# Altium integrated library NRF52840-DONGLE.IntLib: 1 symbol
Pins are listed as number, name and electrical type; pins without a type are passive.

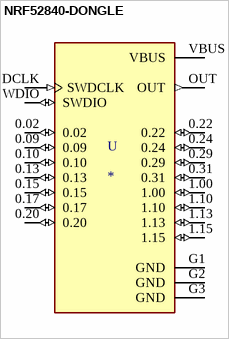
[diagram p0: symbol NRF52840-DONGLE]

## NRF52840-DONGLE
designator U
- Transceiver; BluetoothÂ® 5 For Use With nRF52840; MF: Nordic Semiconductor; MP: NRF52840-DONGLE
footprint MODULE_NRF52840-DONGLE
pins: 0.02 (io), 0.09 (io), 0.10 (io), 0.13 (io), 0.15 (io), 0.17 (io), 0.20 (io), 0.22 (io), 0.24 (io), 0.29 (io), 0.31 (io), 1.00 (io), 1.10 (io), 1.13 (io), 1.15 (io), G1 GND (power), G2 GND (power), G3 GND (power), OUT (out), SWDCLK (in), SWDIO (io), VBUS (power)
